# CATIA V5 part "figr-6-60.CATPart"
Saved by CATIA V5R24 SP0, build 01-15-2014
Part number: Part1
Bounding box of the stored display mesh (mm): x -50.648 to 50.648, y -72.183 to 72.183, z -40 to 40
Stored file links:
  D:\KAVITA\CATIA V5-6R2014 Project_ Kavita\CATIA V5-6R2014_partfiles\Partfiles\c06_catia_v5-6r2014_prt\figr-6-60.CATPart
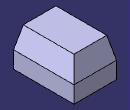
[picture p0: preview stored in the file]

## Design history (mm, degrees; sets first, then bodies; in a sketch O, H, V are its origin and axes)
Body1 (main body)
  Sketch1 on xy-plane, origin (0, 0, 0), H (1, 0, 0), V (0, 1, 0)
    line L1 (-50.6478, 72.1832) -> (50.6478, 72.1832)
    line L2 (50.6478, 72.1832) -> (50.6478, -72.1832)
    line L3 (50.6478, -72.1832) -> (-50.6478, -72.1832)
    line L4 (-50.6478, -72.1832) -> (-50.6478, 72.1832)
    axis line L5 (50.6478, -72.1832) -> (-50.6478, 72.1832)
    horizontal: L1 H, L3 H
    vertical: L2 V, L4 V
    midpoint: O L5
  Pad1: profile Sketch1, direction (0, 0, 1), length 40, mirrored extent
  Draft1: Angle 30, Neutral xy-plane, PullDir (0, 0, 1), SupportToDraft (face of Pad1; face of Pad1)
